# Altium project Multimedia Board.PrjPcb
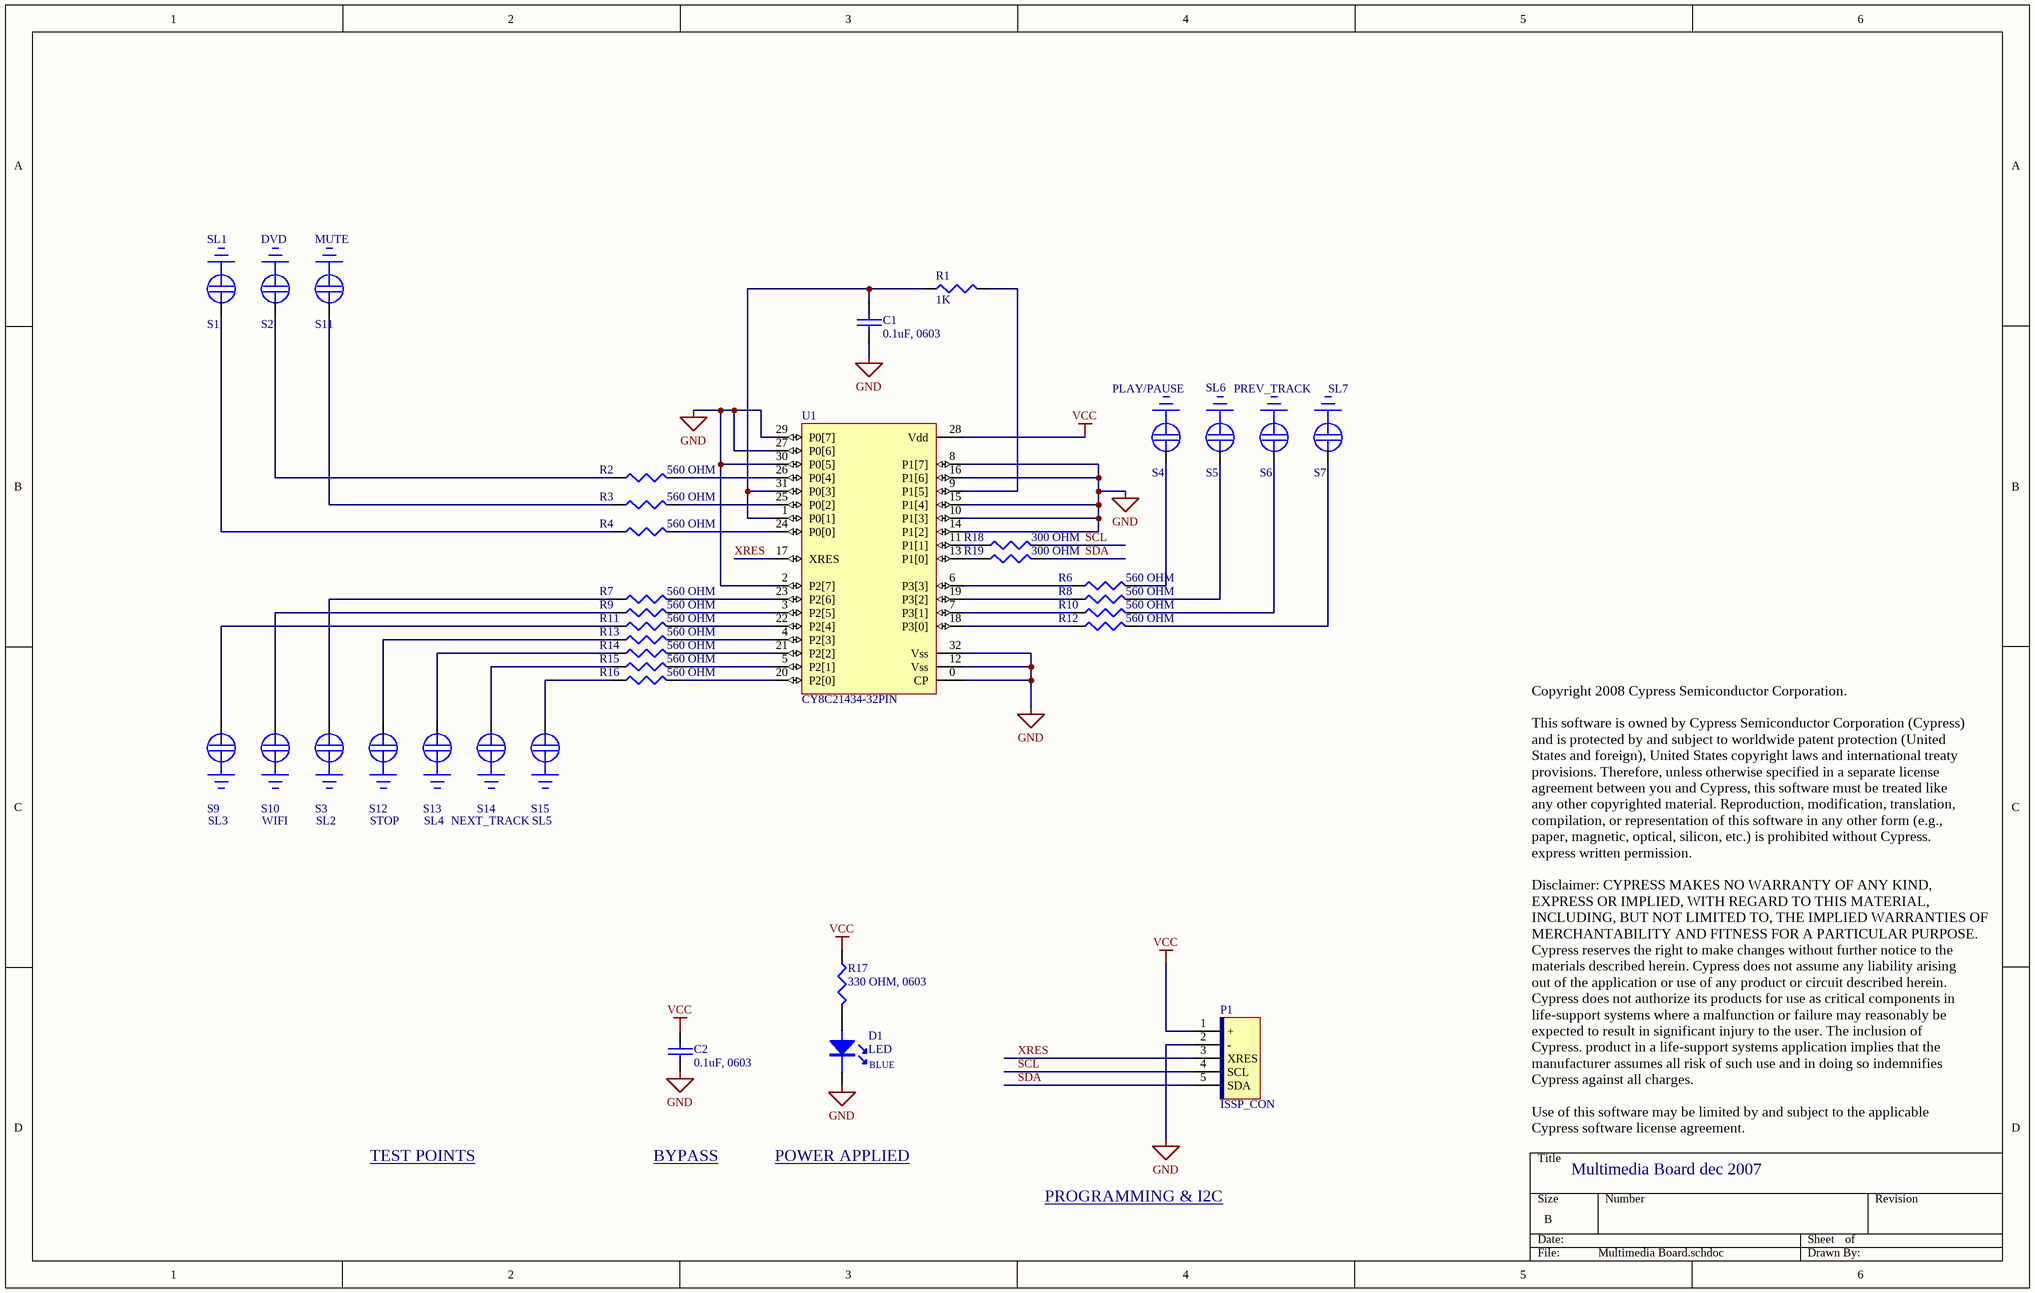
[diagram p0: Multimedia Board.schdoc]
1 sheet, 37 parts. Net scope: global (net labels, ports and power ports of the same name join across sheets).
Board file: Multimedia Board.pcbdoc

## Sheet Multimedia Board.schdoc
size B; PageSetup: Record=PageOptions|CenterHorizontal=True|CenterVertical=True|PrintScale=0.72|XCorrection=1.00|YCorrection=1.00|PrintKind=1|BorderSize=5000000|LeftOffset=0|BottomOffset=0|Orientation=2|PaperLength=1000|PaperWidth=1000|Scale=100|PaperSource=15|PrintQuality=1200|MediaType=1|DitherType=10|PaperKind=Letter|PrintScaleMode=1

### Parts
C1  0.1uF, 0603  [0603]
C2  0.1uF, 0603  [0603]
D1  LED  [0805LED]
P1  ISSP_CON  [ISPCON]
R1  1K  [0603]
R2  560 OHM  [0603]
R3  560 OHM  [0603]
R4  560 OHM  [0603]
R6  560 OHM  [0603]
R7  560 OHM  [0603]
R8  560 OHM  [0603]
R9  560 OHM  [0603]
R10  560 OHM  [0603]
R11  560 OHM  [0603]
R12  560 OHM  [0603]
R13  560 OHM  [0603]
R14  560 OHM  [0603]
R15  560 OHM  [0603]
R16  560 OHM  [0603]
R17  330 OHM, 0603  [0603]
R18  300 OHM  [0603]
R19  300 OHM  [0603]
S1  SL1  [capsense_pad]
S2  DVD  [BUTTON 9mm no silk]
S3  SL2  [CAPSENSE_PAD]
S4  PLAY/PAUSE  [BUTTON 9mm no silk]
S5  SL6  [capsense_pad]
S6  PREV_TRACK  [BUTTON 9mm no silk]
S7  SL7  [capsense_pad]
S9  SL3  [capsense_pad]
S10  WIFI  [BUTTON 9mm no silk]
S11  MUTE  [BUTTON 9mm no silk]
S12  STOP  [BUTTON 9mm no silk]
S13  SL4  [capsense_pad]
S14  NEXT_TRACK  [BUTTON 9mm no silk]
S15  SL5  [capsense_pad]
U1  CY8C21434-32PIN

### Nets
GND: C1.2 C2.2 D1.2(K) P1.2(-) U1.0(CP) U1.2(P2[7]) U1.8(P1[7]) U1.10(P1[3]) U1.12(Vss) U1.14(P1[2]) U1.15(P1[4]) U1.16(P1[6]) U1.27(P0[6]) U1.29(P0[7]) U1.30(P0[5]) U1.32(Vss)
VCC: C2.1 P1.1(+) R17.1 U1.28(Vdd)
SCL: P1.4(SCL) R18.2
SDA: P1.5(SDA) R19.2
XRES: P1.3(XRES) U1.17(XRES)
NetC1_1: C1.1 R1.1 U1.1(P0[1]) U1.31(P0[3])
NetD1_1: D1.1(A) R17.2
NetR1_2: R1.2 U1.9(P1[5])
NetR2_1: R2.1 S2.1
NetR2_2: R2.2 U1.26(P0[4])
NetR3_1: R3.1 S11.1
NetR3_2: R3.2 U1.25(P0[2])
NetR4_1: R4.1 S1.1
NetR4_2: R4.2 U1.24(P0[0])
NetR6_1: R6.1 U1.6(P3[3])
NetR6_2: R6.2 S4.1
NetR7_1: R7.1 S3.1
NetR7_2: R7.2 U1.23(P2[6])
NetR8_1: R8.1 U1.19(P3[2])
NetR8_2: R8.2 S5.1
NetR9_1: R9.1 S10.1
NetR9_2: R9.2 U1.3(P2[5])
NetR10_1: R10.1 U1.7(P3[1])
NetR10_2: R10.2 S6.1
NetR11_1: R11.1 S9.1
NetR11_2: R11.2 U1.22(P2[4])
NetR12_1: R12.1 U1.18(P3[0])
NetR12_2: R12.2 S7.1
NetR13_1: R13.1 S12.1
NetR13_2: R13.2 U1.4(P2[3])
NetR14_1: R14.1 S13.1
NetR14_2: R14.2 U1.21(P2[2])
NetR15_1: R15.1 S14.1
NetR15_2: R15.2 U1.5(P2[1])
NetR16_1: R16.1 S15.1
NetR16_2: R16.2 U1.20(P2[0])
NetR18_1: R18.1 U1.11(P1[1])
NetR19_1: R19.1 U1.13(P1[0])

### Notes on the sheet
- (near D1) BLUE
- TEST POINTS
- BYPASS
- POWER APPLIED
- Copyright 2008 Cypress Semiconductor Corporation.
  This software is owned by Cypress Semiconductor Corporation (Cypress)
  and is protected by and subject to worldwide patent protection (United
  States and foreign), United States copyright laws and international treaty
  provisions. Therefore, unless otherwise specified in a separate license
  agreement between you and Cypress, this software must be treated like
  any other copyrighted material. Reproduction, modification, translation,
  compilation, or representation of this software in any other form (e.g.,
  paper, magnetic, optical, silicon, etc.) is prohibited without Cypress.
  express written permission.
  Disclaimer: CYPRESS MAKES NO WARRANTY OF ANY KIND,
  EXPRESS OR IMPLIED, WITH REGARD TO THIS MATERIAL,
  INCLUDING, BUT NOT LIMITED TO, THE IMPLIED WARRANTIES OF
  MERCHANTABILITY AND FITNESS FOR A PARTICULAR PURPOSE.
  Cypress reserves the right to make changes without further notice to the
  materials described herein. Cypress does not assume any liability arising
  out of the application or use of any product or circuit described herein.
  Cypress does not authorize its products for use as critical components in
  life-support systems where a malfunction or failure may reasonably be
  expected to result in significant injury to the user. The inclusion of
  Cypress. product in a life-support systems application implies that the
  manufacturer assumes all risk of such use and in doing so indemnifies
  Cypress against all charges.
  Use of this software may be limited by and subject to the applicable
  Cypress software license agreement.
- Multimedia Board dec 2007
- PROGRAMMING & I2C

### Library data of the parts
C1 C2 = CAP: Capacitor; Vender: Digikey; VPN: PCC1864TR-ND
D1 = LED: BLUE
P1 = ISSP_CON: PSoC Programming Connector; Vender: Digikey
R1-R4 R6-R19 = RES: RESISTOR
S1-S7 S9-S15 = CAPSENSE BUTTON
